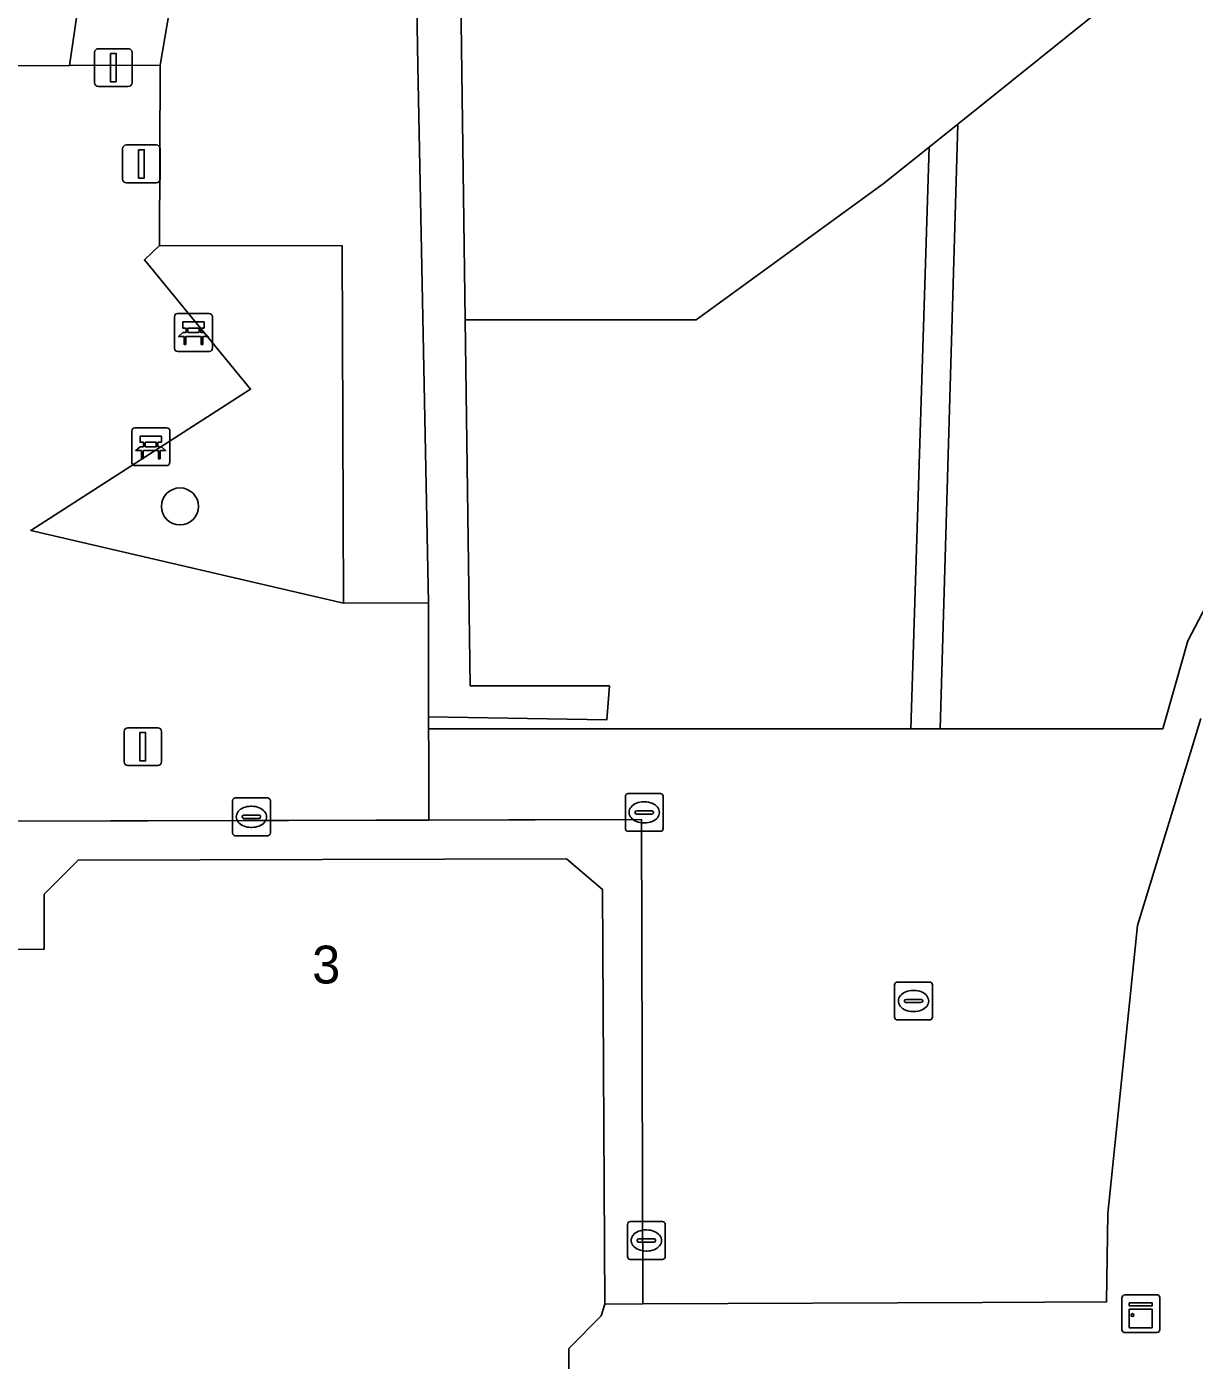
# Model space of a CAD drawing. Extents: x 160203 to 161530, y 379528 to 381797.
# Drawn here: x 160887.38 to 160918.26, y 380733.92 to 380769.2 of the extents above; entities that cross this region are included whole.
import ezdxf

# ---------------------------------------------------------------- set-up
doc = ezdxf.new("R2010")
doc.units = 0
for name, color, linetype in [('IMGEO_Afsluitpaal', 7, 'Continuous'), ('IMGEO_Bank', 7, 'Continuous'), ('IMGEO_Boom', 7, 'Continuous'), ('IMGEO_Groenvoorziening', 7, 'Continuous'), ('IMGEO_Haag', 7, 'Continuous'), ('IMGEO_Hek', 7, 'Continuous'), ('IMGEO_Kast', 7, 'Continuous'), ('IMGEO_Kolk', 7, 'Continuous'), ('IMGEO_Lichtmast', 7, 'Continuous'), ('IMGEO_Pand', 7, 'Continuous'), ('IMGEO_Pand_nummerreeks', 7, 'Continuous'), ('IMGEO_Pand_overbouw', 7, 'Continuous'), ('IMGEO_Parkeervlak_open', 7, 'Continuous'), ('IMGEO_Voetpad_open', 7, 'Continuous')]:
    doc.layers.add(name, color=color, linetype=linetype)

msp = doc.modelspace()

# ---------------------------------------------------------------- linework, layer by layer
at = {"layer": 'IMGEO_Afsluitpaal'}
for p, q in [((160889.179, 380767.721), (160889.179, 380768.521)), ((160889.179, 380768.521), (160889.179, 380767.721)), ((160889.279, 380768.621), (160890.069, 380768.621)), ((160890.069, 380768.621), (160889.279, 380768.621)), ((160890.169, 380768.521), (160890.169, 380767.721)), ((160890.169, 380767.721), (160890.169, 380768.521)), ((160890.069, 380767.621), (160889.279, 380767.621)), ((160889.279, 380767.621), (160890.069, 380767.621))]:
    msp.add_line(p, q, dxfattribs=at)
msp.add_lwpolyline([(160889.599, 380768.496), (160889.749, 380768.496), (160889.749, 380767.746), (160889.599, 380767.746), (160889.599, 380768.496)], dxfattribs=at)
for centre, start, end in [((160889.279, 380768.521), 90, 180), ((160889.279, 380768.521), 90, 180), ((160890.069, 380768.521), 0, 90), ((160890.069, 380768.521), 360, 90), ((160889.279, 380767.721), 180, 270), ((160889.279, 380767.721), 180, 270), ((160890.069, 380767.721), 270, 0), ((160890.069, 380767.721), 270, 0)]:
    msp.add_arc(centre, 0.1, start, end, dxfattribs=at)
at = {"layer": 'IMGEO_Bank'}
for p, q in [((160891.294, 380760.687), (160891.294, 380761.528)), ((160891.294, 380761.528), (160891.294, 380760.687)), ((160891.369, 380761.612), (160892.21, 380761.612)), ((160892.21, 380761.612), (160891.369, 380761.612)), ((160892.294, 380761.537), (160892.294, 380760.696)), ((160892.294, 380760.696), (160892.294, 380761.537)), ((160891.603, 380761.118), (160891.603, 380761.224)), ((160891.647, 380761.224), (160891.647, 380761.118)), ((160891.935, 380761.23), (160891.653, 380761.23)), ((160891.653, 380761.112), (160891.935, 380761.112)), ((160891.941, 380761.118), (160891.941, 380761.224)), ((160891.985, 380761.224), (160891.985, 380761.118)), ((160891.991, 380761.01), (160891.598, 380761.01)), ((160892.219, 380760.612), (160891.378, 380760.612)), ((160891.378, 380760.612), (160892.219, 380760.612)), ((160890.165, 380757.665), (160890.165, 380758.506)), ((160890.165, 380758.506), (160890.165, 380757.665)), ((160890.24, 380758.59), (160891.081, 380758.59)), ((160891.081, 380758.59), (160890.24, 380758.59)), ((160891.165, 380758.515), (160891.165, 380757.674)), ((160891.165, 380757.674), (160891.165, 380758.515)), ((160890.862, 380757.988), (160890.469, 380757.988)), ((160890.474, 380758.096), (160890.474, 380758.202)), ((160890.518, 380758.202), (160890.518, 380758.096)), ((160890.806, 380758.208), (160890.524, 380758.208)), ((160890.524, 380758.09), (160890.806, 380758.09)), ((160890.812, 380758.096), (160890.812, 380758.202)), ((160890.856, 380758.202), (160890.856, 380758.096)), ((160891.09, 380757.59), (160890.249, 380757.59)), ((160890.249, 380757.59), (160891.09, 380757.59))]:
    msp.add_line(p, q, dxfattribs=at)
for points in [[(160891.541, 380761.01), (160891.399, 380761.01), (160891.511, 380761.112), (160891.597, 380761.112)], [(160891.597, 380761.23), (160891.511, 380761.23), (160891.511, 380761.391), (160892.074, 380761.391), (160892.074, 380761.23), (160891.991, 380761.23)], [(160891.991, 380761.112), (160892.074, 380761.112), (160892.186, 380761.01), (160892.047, 380761.01)], [(160891.591, 380761.003), (160891.591, 380760.796), (160891.548, 380760.796), (160891.548, 380761.003)], [(160892.041, 380761.003), (160892.041, 380760.796), (160891.997, 380760.796), (160891.997, 380761.003)], [(160890.468, 380758.208), (160890.382, 380758.208), (160890.382, 380758.369), (160890.945, 380758.369), (160890.945, 380758.208), (160890.862, 380758.208)], [(160890.412, 380757.988), (160890.27, 380757.988), (160890.382, 380758.09), (160890.468, 380758.09)], [(160890.462, 380757.981), (160890.462, 380757.774), (160890.419, 380757.774), (160890.419, 380757.981)], [(160890.862, 380758.09), (160890.945, 380758.09), (160891.057, 380757.988), (160890.918, 380757.988)], [(160890.912, 380757.981), (160890.912, 380757.774), (160890.868, 380757.774), (160890.868, 380757.981)]]:
    msp.add_lwpolyline(points, dxfattribs=at)
for centre, radius, start, end in [((160891.372, 380761.534), 0.0779, 92.4484, 184.2845), ((160891.372, 380761.534), 0.0779, 92.4484, 184.2845), ((160892.216, 380761.534), 0.0779, 2.4484, 94.2845), ((160892.216, 380761.534), 0.0779, 2.4484, 94.2845), ((160891.596, 380761.223), 0.00671, 2.8957, 87.1043), ((160891.596, 380761.119), 0.00671, 272.8957, 357.1043), ((160891.653, 380761.223), 0.00671, 92.8957, 177.1043), ((160891.653, 380761.119), 0.00671, 182.8957, 267.1043), ((160891.935, 380761.223), 0.00671, 2.8957, 87.1043), ((160891.935, 380761.119), 0.00671, 272.8957, 357.1043), ((160891.992, 380761.223), 0.00671, 92.8957, 177.1043), ((160891.992, 380761.119), 0.00671, 182.8957, 267.1043), ((160891.541, 380761.003), 0.00671, 2.8957, 87.1043), ((160891.598, 380761.003), 0.00671, 92.8957, 177.1043), ((160891.99, 380761.003), 0.00671, 2.8957, 87.1043), ((160892.047, 380761.003), 0.00671, 92.8957, 177.1043), ((160891.372, 380760.69), 0.0779, 182.4484, 274.2845), ((160891.372, 380760.69), 0.0779, 182.4484, 274.2845), ((160892.216, 380760.69), 0.0779, 272.4484, 4.2845), ((160892.216, 380760.69), 0.0779, 272.4484, 4.2845), ((160890.243, 380758.512), 0.0779, 92.4484, 184.2845), ((160890.243, 380758.512), 0.0779, 92.4484, 184.2845), ((160891.087, 380758.512), 0.0779, 2.4484, 94.2845), ((160891.087, 380758.512), 0.0779, 2.4484, 94.2845), ((160890.412, 380757.981), 0.00671, 2.8957, 87.1043), ((160890.469, 380757.981), 0.00671, 92.8957, 177.1043), ((160890.467, 380758.201), 0.00671, 2.8957, 87.1043), ((160890.467, 380758.097), 0.00671, 272.8957, 357.1043), ((160890.524, 380758.201), 0.00671, 92.8957, 177.1043), ((160890.524, 380758.097), 0.00671, 182.8957, 267.1043), ((160890.806, 380758.201), 0.00671, 2.8957, 87.1043), ((160890.806, 380758.097), 0.00671, 272.8957, 357.1043), ((160890.863, 380758.201), 0.00671, 92.8957, 177.1043), ((160890.863, 380758.097), 0.00671, 182.8957, 267.1043), ((160890.861, 380757.981), 0.00671, 2.8957, 87.1043), ((160890.918, 380757.981), 0.00671, 92.8957, 177.1043), ((160890.243, 380757.668), 0.0779, 182.4484, 274.2845), ((160890.243, 380757.668), 0.0779, 182.4484, 274.2845), ((160891.087, 380757.668), 0.0779, 272.4484, 4.2845), ((160891.087, 380757.668), 0.0779, 272.4484, 4.2845)]:
    msp.add_arc(centre, radius, start, end, dxfattribs=at)
at = {"layer": 'IMGEO_Boom'}
msp.add_circle((160891.437, 380756.513), 0.489, dxfattribs=at)
at = {"layer": 'IMGEO_Groenvoorziening'}
for points in [[(160898.011, 380750.946), (160902.722, 380750.865), (160902.791, 380751.765), (160899.115, 380751.765), (160898.983, 380761.45), (160898.69, 380783.066), (160932.839, 380790.308), (160952.53, 380794.484), (160966.254, 380797.667), (160978.035, 380800.148), (160981.545, 380801.036), (160981.566, 380799.472), (160982.767, 380793.847), (160983.572, 380794.021), (160981.979, 380801.73), (160921.845, 380789.002), (160897.464, 380783.841), (160897.497, 380781.89), (160897.729, 380768.163), (160898.011, 380753.96)], [(160905.086, 380761.45), (160910.031, 380765.042), (160911.248, 380766.02), (160912.004, 380766.626), (160933.337, 380783.757), (160932.839, 380790.308), (160898.69, 380783.066), (160898.983, 380761.45)], [(160898.011, 380753.96), (160897.729, 380768.163), (160897.497, 380781.89), (160897.464, 380783.841), (160892.435, 380777.138), (160890.911, 380768.187), (160890.894, 380763.417), (160895.724, 380763.408), (160895.762, 380753.954)], [(160889.865, 380777.392), (160888.533, 380781.612), (160888.428, 380781.929), (160888.317, 380781.905), (160862.044, 380776.218), (160863.278, 380770.473), (160860.088, 380769.786), (160858.834, 380775.541), (160857.114, 380775.173), (160857.128, 380767.765), (160859.443, 380767.782), (160859.472, 380765.525), (160863.523, 380765.538), (160868.849, 380765.538), (160871.481, 380765.511), (160871.481, 380765.528), (160871.541, 380768.117), (160875.906, 380768.117), (160885.697, 380768.163), (160888.514, 380768.176)], [(160911.248, 380766.02), (160910.766, 380750.632), (160911.54, 380750.632), (160912.004, 380766.626)], [(160898.983, 380761.45), (160899.115, 380751.765), (160902.791, 380751.765), (160902.722, 380750.865), (160898.011, 380750.946), (160898.011, 380750.766), (160898.011, 380750.632), (160910.766, 380750.632), (160911.248, 380766.02), (160910.031, 380765.042), (160905.086, 380761.45)], [(160895.724, 380763.408), (160890.894, 380763.417), (160890.496, 380763.038), (160893.305, 380759.611), (160887.493, 380755.875), (160895.762, 380753.954)]]:
    msp.add_lwpolyline(points, close=True, dxfattribs=at)
msp.add_lwpolyline([(160933.337, 380783.757), (160912.004, 380766.626), (160911.54, 380750.632), (160914.783, 380750.632), (160917.427, 380750.632), (160917.733, 380751.709), (160918.088, 380752.958), (160921.971, 380760.385)], dxfattribs=at)
at = {"layer": 'IMGEO_Haag'}
for points in [[(160898.011, 380750.946), (160902.722, 380750.865), (160902.791, 380751.765), (160899.115, 380751.765), (160898.983, 380761.45), (160898.69, 380783.066), (160932.839, 380790.308), (160952.53, 380794.484), (160966.254, 380797.667), (160978.035, 380800.148), (160981.545, 380801.036), (160981.566, 380799.472), (160982.767, 380793.847), (160983.572, 380794.021), (160981.979, 380801.73), (160921.845, 380789.002), (160897.464, 380783.841), (160897.497, 380781.89), (160897.729, 380768.163), (160898.011, 380753.96)], [(160911.248, 380766.02), (160910.766, 380750.632), (160911.54, 380750.632), (160912.004, 380766.626)]]:
    msp.add_lwpolyline(points, close=True, dxfattribs=at)
at = {"layer": 'IMGEO_Hek'}
for points in [[(160897.729, 380768.163), (160897.497, 380781.89)], [(160897.729, 380768.163), (160898.011, 380753.96)]]:
    msp.add_lwpolyline(points, dxfattribs=at)
at = {"layer": 'IMGEO_Kast'}
for p, q in [((160916.346, 380734.732), (160916.346, 380735.573)), ((160916.346, 380735.573), (160916.346, 380734.732)), ((160916.421, 380735.657), (160917.262, 380735.657)), ((160917.262, 380735.657), (160916.421, 380735.657)), ((160917.346, 380735.582), (160917.346, 380734.741)), ((160917.346, 380734.741), (160917.346, 380735.582)), ((160917.271, 380734.657), (160916.43, 380734.657)), ((160916.43, 380734.657), (160917.271, 380734.657))]:
    msp.add_line(p, q, dxfattribs=at)
for points in [[(160916.541, 380735.447), (160917.141, 380735.447), (160917.141, 380735.362), (160916.541, 380735.362), (160916.541, 380735.447)], [(160916.541, 380735.272), (160917.141, 380735.272), (160917.141, 380734.783), (160916.541, 380734.783), (160916.541, 380735.272)]]:
    msp.add_lwpolyline(points, dxfattribs=at)
msp.add_circle((160916.625, 380735.121), 0.0377, dxfattribs=at)
for centre, start, end in [((160916.424, 380735.579), 92.4484, 184.2845), ((160916.424, 380735.579), 92.4484, 184.2845), ((160917.268, 380735.579), 2.4484, 94.2845), ((160917.268, 380735.579), 2.4484, 94.2845), ((160916.424, 380734.735), 182.4484, 274.2845), ((160916.424, 380734.735), 182.4484, 274.2845), ((160917.268, 380734.735), 272.4484, 4.2845), ((160917.268, 380734.735), 272.4484, 4.2845)]:
    msp.add_arc(centre, 0.0779, start, end, dxfattribs=at)
at = {"layer": 'IMGEO_Kolk'}
for p, q in [((160892.901, 380748.8), (160893.753, 380748.8)), ((160903.214, 380747.991), (160903.214, 380748.843)), ((160903.289, 380748.917), (160904.141, 380748.917)), ((160904.215, 380748.843), (160904.215, 380747.991)), ((160892.826, 380747.874), (160892.826, 380748.726)), ((160893.314, 380748.58), (160893.339, 380748.58)), ((160893.827, 380748.726), (160893.827, 380747.874)), ((160903.473, 380748.411), (160903.473, 380748.423)), ((160903.516, 380748.46), (160903.914, 380748.46)), ((160903.702, 380748.697), (160903.727, 380748.697)), ((160903.957, 380748.423), (160903.957, 380748.411)), ((160893.085, 380748.294), (160893.085, 380748.306)), ((160893.523, 380748.257), (160893.125, 380748.257)), ((160893.128, 380748.343), (160893.526, 380748.343)), ((160893.569, 380748.306), (160893.569, 380748.294)), ((160903.911, 380748.374), (160903.513, 380748.374)), ((160903.725, 380748.137), (160903.7, 380748.137)), ((160893.753, 380747.8), (160892.901, 380747.8)), ((160893.337, 380748.02), (160893.312, 380748.02)), ((160904.141, 380747.917), (160903.289, 380747.917)), ((160910.334, 380743.002), (160910.334, 380743.854)), ((160910.409, 380743.928), (160911.261, 380743.928)), ((160911.335, 380743.854), (160911.335, 380743.002)), ((160910.636, 380743.471), (160911.034, 380743.471)), ((160910.822, 380743.708), (160910.847, 380743.708)), ((160910.593, 380743.422), (160910.593, 380743.434)), ((160911.031, 380743.385), (160910.633, 380743.385)), ((160910.845, 380743.148), (160910.82, 380743.148)), ((160911.077, 380743.434), (160911.077, 380743.422)), ((160911.261, 380742.928), (160910.409, 380742.928)), ((160903.269, 380736.667), (160903.269, 380737.519)), ((160903.344, 380737.593), (160904.196, 380737.593)), ((160904.27, 380737.519), (160904.27, 380736.667)), ((160903.528, 380737.087), (160903.528, 380737.099)), ((160903.571, 380737.136), (160903.969, 380737.136)), ((160903.757, 380737.373), (160903.782, 380737.373)), ((160904.012, 380737.099), (160904.012, 380737.087)), ((160903.966, 380737.05), (160903.568, 380737.05)), ((160903.78, 380736.813), (160903.755, 380736.813)), ((160904.196, 380736.593), (160903.344, 380736.593))]:
    msp.add_line(p, q, dxfattribs=at)
for points in [[(160892.901, 380748.8), (160893.753, 380748.8)], [(160903.214, 380747.991), (160903.214, 380748.843)], [(160903.289, 380748.917), (160904.141, 380748.917)], [(160904.215, 380748.843), (160904.215, 380747.991)], [(160892.826, 380747.874), (160892.826, 380748.726)], [(160893.827, 380748.726), (160893.827, 380747.874)], [(160893.753, 380747.8), (160892.901, 380747.8)], [(160904.141, 380747.917), (160903.289, 380747.917)], [(160910.334, 380743.002), (160910.334, 380743.854)], [(160910.409, 380743.928), (160911.261, 380743.928)], [(160911.335, 380743.854), (160911.335, 380743.002)], [(160911.261, 380742.928), (160910.409, 380742.928)], [(160903.269, 380736.667), (160903.269, 380737.519)], [(160903.344, 380737.593), (160904.196, 380737.593)], [(160904.27, 380737.519), (160904.27, 380736.667)], [(160904.196, 380736.593), (160903.344, 380736.593)]]:
    msp.add_lwpolyline(points, dxfattribs=at)
for centre, radius, start, end in [((160892.903, 380748.724), 0.0765, 91.552, 178.448), ((160892.903, 380748.724), 0.0765, 91.552, 178.448), ((160893.751, 380748.724), 0.0765, 1.552, 88.448), ((160893.751, 380748.724), 0.0765, 1.552, 88.448), ((160903.291, 380748.841), 0.0765, 91.552, 178.448), ((160903.291, 380748.841), 0.0765, 91.552, 178.448), ((160904.139, 380748.841), 0.0765, 1.552, 88.448), ((160904.139, 380748.841), 0.0765, 1.552, 88.448), ((160903.513, 380748.42), 0.0403, 85.8775, 175.7526), ((160903.51, 380748.41), 0.0366, 178.938, 274.7102), ((160903.914, 380748.417), 0.043, 264.8664, 352.4533), ((160903.918, 380748.422), 0.0386, 1.7309, 96.639), ((160893.125, 380748.303), 0.0403, 85.8775, 175.7526), ((160893.122, 380748.293), 0.0366, 178.938, 274.7102), ((160893.526, 380748.3), 0.043, 264.8664, 352.4533), ((160893.53, 380748.305), 0.0386, 1.7309, 96.639), ((160892.903, 380747.876), 0.0765, 181.552, 268.448), ((160892.903, 380747.876), 0.0765, 181.552, 268.448), ((160893.751, 380747.876), 0.0765, 271.552, 358.448), ((160893.751, 380747.876), 0.0765, 271.552, 358.448), ((160903.291, 380747.993), 0.0765, 181.552, 268.448), ((160903.291, 380747.993), 0.0765, 181.552, 268.448), ((160904.139, 380747.993), 0.0765, 271.552, 358.448), ((160904.139, 380747.993), 0.0765, 271.552, 358.448), ((160910.411, 380743.852), 0.0765, 91.552, 178.448), ((160910.411, 380743.852), 0.0765, 91.552, 178.448), ((160911.259, 380743.852), 0.0765, 1.552, 88.448), ((160911.259, 380743.852), 0.0765, 1.552, 88.448), ((160910.633, 380743.431), 0.0403, 85.8775, 175.7526), ((160911.038, 380743.433), 0.0386, 1.7309, 96.639), ((160910.63, 380743.421), 0.0366, 178.938, 274.7102), ((160911.034, 380743.428), 0.043, 264.8664, 352.4533), ((160910.411, 380743.004), 0.0765, 181.552, 268.448), ((160910.411, 380743.004), 0.0765, 181.552, 268.448), ((160911.259, 380743.004), 0.0765, 271.552, 358.448), ((160911.259, 380743.004), 0.0765, 271.552, 358.448), ((160903.346, 380737.517), 0.0765, 91.552, 178.448), ((160903.346, 380737.517), 0.0765, 91.552, 178.448), ((160904.194, 380737.517), 0.0765, 1.552, 88.448), ((160904.194, 380737.517), 0.0765, 1.552, 88.448), ((160903.568, 380737.096), 0.0403, 85.8775, 175.7526), ((160903.973, 380737.098), 0.0386, 1.7309, 96.639), ((160903.565, 380737.086), 0.0366, 178.938, 274.7102), ((160903.969, 380737.093), 0.043, 264.8664, 352.4533), ((160903.346, 380736.669), 0.0765, 181.552, 268.448), ((160903.346, 380736.669), 0.0765, 181.552, 268.448), ((160904.194, 380736.669), 0.0765, 271.552, 358.448), ((160904.194, 380736.669), 0.0765, 271.552, 358.448)]:
    msp.add_arc(centre, radius, start, end, dxfattribs=at)
for centre, major_axis, ratio, start_param, end_param in [((160893.313, 380748.3), (-0.387, 0.002), 0.722429, 4.712389, 7.853982), ((160893.338, 380748.3), (-0.39, 0.002), 0.717154, 1.570796, 4.712389), ((160903.701, 380748.417), (-0.387, 0.002), 0.722429, 4.712389, 7.853982), ((160903.726, 380748.417), (-0.39, 0.002), 0.717154, 1.570796, 4.712389), ((160910.821, 380743.428), (-0.387, 0.002), 0.722429, 4.712389, 7.853982), ((160910.846, 380743.428), (-0.39, 0.002), 0.717154, 1.570796, 4.712389), ((160903.756, 380737.093), (-0.387, 0.002), 0.722429, 4.712389, 7.853982), ((160903.781, 380737.093), (-0.39, 0.002), 0.717154, 1.570796, 4.712389)]:
    msp.add_ellipse(centre, major_axis=major_axis, ratio=ratio, start_param=start_param, end_param=end_param, dxfattribs=at)
at = {"layer": 'IMGEO_Lichtmast'}
for p, q in [((160890.021, 380766.073), (160890.811, 380766.073)), ((160890.811, 380766.073), (160890.021, 380766.073)), ((160889.921, 380765.173), (160889.921, 380765.973)), ((160889.921, 380765.973), (160889.921, 380765.173)), ((160890.911, 380765.973), (160890.911, 380765.173)), ((160890.911, 380765.173), (160890.911, 380765.973)), ((160890.811, 380765.073), (160890.021, 380765.073)), ((160890.021, 380765.073), (160890.811, 380765.073)), ((160889.96, 380749.755), (160889.96, 380750.555)), ((160889.96, 380750.555), (160889.96, 380749.755)), ((160890.06, 380750.655), (160890.85, 380750.655)), ((160890.85, 380750.655), (160890.06, 380750.655)), ((160890.95, 380750.555), (160890.95, 380749.755)), ((160890.95, 380749.755), (160890.95, 380750.555)), ((160890.85, 380749.655), (160890.06, 380749.655)), ((160890.06, 380749.655), (160890.85, 380749.655))]:
    msp.add_line(p, q, dxfattribs=at)
for points in [[(160890.341, 380765.948), (160890.491, 380765.948), (160890.491, 380765.198), (160890.341, 380765.198), (160890.341, 380765.948)], [(160890.38, 380750.53), (160890.53, 380750.53), (160890.53, 380749.78), (160890.38, 380749.78), (160890.38, 380750.53)]]:
    msp.add_lwpolyline(points, dxfattribs=at)
for centre, start, end in [((160890.021, 380765.973), 90, 180), ((160890.021, 380765.973), 90, 180), ((160890.811, 380765.973), 0, 90), ((160890.811, 380765.973), 360, 90), ((160890.021, 380765.173), 180, 270), ((160890.021, 380765.173), 180, 270), ((160890.811, 380765.173), 270, 0), ((160890.811, 380765.173), 270, 0), ((160890.06, 380750.555), 90, 180), ((160890.06, 380750.555), 90, 180), ((160890.85, 380750.555), 0, 90), ((160890.85, 380750.555), 360, 90), ((160890.06, 380749.755), 180, 270), ((160890.06, 380749.755), 180, 270), ((160890.85, 380749.755), 270, 0), ((160890.85, 380749.755), 270, 0)]:
    msp.add_arc(centre, 0.1, start, end, dxfattribs=at)
at = {"layer": 'IMGEO_Pand'}
for points in [[(160918.433, 380750.903), (160918.157, 380750), (160916.758, 380745.422), (160915.974, 380737.805), (160915.94, 380735.467), (160912.662, 380735.453), (160903.673, 380735.416), (160902.67, 380735.412), (160902.579, 380735.097), (160901.722, 380734.236), (160901.731, 380730.795), (160903.685, 380730.806), (160904.4, 380730.81), (160905.281, 380729.901), (160905.353, 380721.078), (160904.452, 380720.135), (160903.712, 380720.133), (160903.778, 380695.064), (160899.698, 380695.053), (160899.756, 380645.422)], [(160901.731, 380730.795), (160901.722, 380734.236), (160902.579, 380735.097), (160902.67, 380735.412), (160902.609, 380746.38), (160901.659, 380747.188), (160888.743, 380747.155), (160887.844, 380746.251), (160887.848, 380744.803), (160883.018, 380744.79), (160883.015, 380745.662), (160880.743, 380745.657), (160880.744, 380745.18), (160877.98, 380745.173), (160875.134, 380742.312), (160875.142, 380739.544), (160874.628, 380739.543), (160874.635, 380737.172), (160875.597, 380737.175), (160875.647, 380717.982)]]:
    msp.add_lwpolyline(points, dxfattribs=at)
at = {"layer": 'IMGEO_Pand_overbouw'}
msp.add_lwpolyline([(160875.647, 380717.982), (160875.597, 380737.175), (160874.635, 380737.172), (160874.628, 380739.543), (160875.142, 380739.544), (160875.134, 380742.312), (160877.98, 380745.173), (160880.744, 380745.18), (160880.743, 380745.657), (160883.015, 380745.662), (160883.018, 380744.79), (160887.848, 380744.803), (160887.844, 380746.251), (160888.743, 380747.155), (160901.659, 380747.188), (160902.609, 380746.38), (160902.67, 380735.412), (160903.673, 380735.416), (160903.639, 380748.231), (160872.029, 380748.148), (160872.107, 380718.502)], dxfattribs=at)
at = {"layer": 'IMGEO_Parkeervlak_open'}
msp.add_lwpolyline([(160872.029, 380748.148), (160898.017, 380748.216), (160898.019, 380750), (160898.011, 380750.632), (160898.011, 380750.766), (160898.011, 380750.946), (160898.011, 380753.96), (160895.762, 380753.954), (160887.493, 380755.875), (160893.305, 380759.611), (160890.496, 380763.038), (160890.894, 380763.417), (160890.911, 380768.187), (160888.514, 380768.176), (160885.697, 380768.163)], dxfattribs=at)
at = {"layer": 'IMGEO_Voetpad_open'}
msp.add_lwpolyline([(160897.464, 380783.841), (160888.428, 380781.929), (160888.533, 380781.612), (160889.865, 380777.392), (160888.514, 380768.176), (160890.911, 380768.187), (160892.435, 380777.138)], close=True, dxfattribs=at)
for points in [[(160921.971, 380760.385), (160918.088, 380752.958), (160917.733, 380751.709), (160917.427, 380750.632), (160914.783, 380750.632), (160911.54, 380750.632), (160910.766, 380750.632), (160898.011, 380750.632), (160898.019, 380750), (160898.017, 380748.216), (160903.639, 380748.231), (160903.673, 380735.416), (160912.662, 380735.453), (160915.94, 380735.467), (160915.974, 380737.805), (160916.758, 380745.422), (160918.157, 380750), (160918.433, 380750.903)], [(160875.647, 380717.982), (160875.597, 380737.175), (160874.635, 380737.172), (160874.628, 380739.543), (160875.142, 380739.544), (160875.134, 380742.312), (160877.98, 380745.173), (160880.744, 380745.18), (160880.743, 380745.657), (160883.015, 380745.662), (160883.018, 380744.79), (160887.848, 380744.803), (160887.844, 380746.251), (160888.743, 380747.155), (160901.659, 380747.188), (160902.609, 380746.38), (160902.67, 380735.412), (160903.673, 380735.416), (160903.639, 380748.231), (160898.017, 380748.216), (160872.029, 380748.148), (160872.107, 380718.502)]]:
    msp.add_lwpolyline(points, dxfattribs=at)

# ---------------------------------------------------------------- texts
at = {"layer": 'IMGEO_Pand_nummerreeks'}
msp.add_text('3', height=1, rotation=0.1464, dxfattribs=at).set_placement((160894.934, 380743.891))

doc.saveas('drawing.dxf')
